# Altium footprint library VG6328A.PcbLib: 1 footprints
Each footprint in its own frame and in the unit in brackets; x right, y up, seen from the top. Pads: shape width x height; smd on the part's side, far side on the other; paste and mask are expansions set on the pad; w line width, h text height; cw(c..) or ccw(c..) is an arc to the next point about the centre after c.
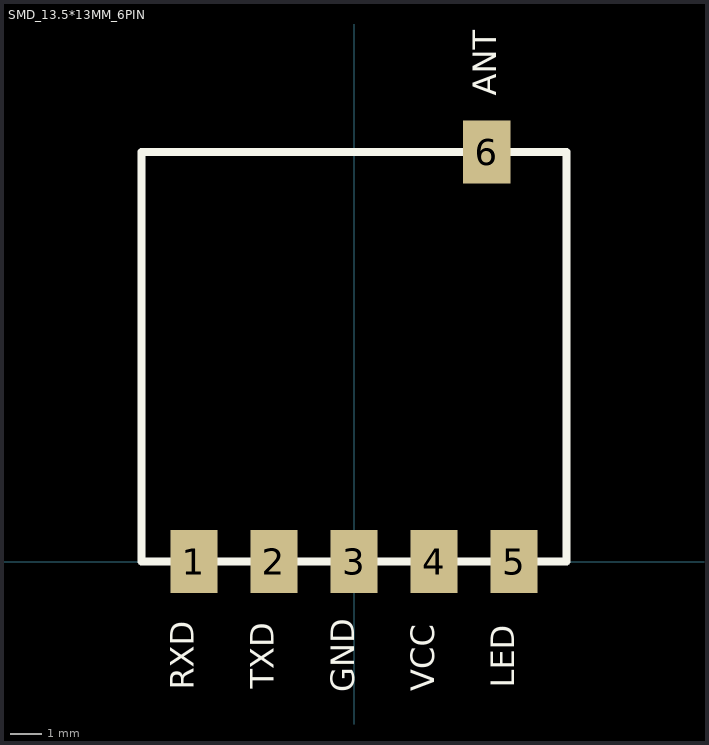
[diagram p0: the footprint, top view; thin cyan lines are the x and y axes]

## SMD_13.5*13MM_6PIN [mm]
pads (6):
  rect 1.5x2 smd paste+0: 1(-5.08,0) 2(-2.54,0) 3(0,0) 4(2.54,0) 5(5.08,0) 6(4.21,13)
Top Overlay:
  lines w0.254: -6.75,0 -6.75,13 6.75,13 6.75,0 -6.75,0
  text "ANT" at 4.768,14.782 h1.27
  text "LED" at 5.334,-3.999 h1.27
  text "VCC" at 2.795,-4.104 h1.27
  text "GND" at 0.254,-4.141 h1.27
  text "TXD" at -2.286,-4.03 h1.27
  text "RXD" at -4.826,-4.064 h1.27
